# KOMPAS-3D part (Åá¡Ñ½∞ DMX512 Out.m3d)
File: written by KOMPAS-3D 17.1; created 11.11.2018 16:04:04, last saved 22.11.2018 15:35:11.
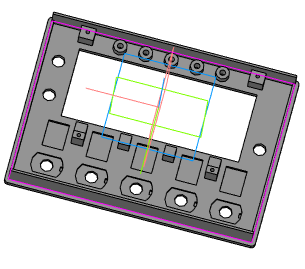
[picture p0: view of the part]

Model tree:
1. Эскиз:1
2. Элемент выдавливания:1
     Расстояние 1 = 2.4
3. Эскиз:2
4. Элемент выдавливания:2
     Расстояние 2 = 0.8
5. Эскиз:3
6. Элемент выдавливания:4
     Расстояние 2 = 2.2
7. Эскиз:4
8. Элемент выдавливания:5
     Расстояние 2 = 1
9. Эскиз:5
10. Элемент выдавливания:6
     Расстояние 1 = 3.9
11. Эскиз:6
12. Элемент выдавливания:7
     Расстояние 2 = 5.5
13. Эскиз:7
14. Элемент выдавливания:8
     Расстояние 2 = 5.5
15. Эскиз:8
16. Элемент выдавливания:9
     Расстояние 1 = 7.1
17. Эскиз:9
18. Элемент выдавливания:10
     Расстояние 2 = 7
19. Эскиз:10
20. Элемент выдавливания:11
     Расстояние 1 = 1.65
21. Эскиз:11
22. Элемент выдавливания:12
     Расстояние 2 = 7
23. Эскиз:12
24. Элемент выдавливания:13
     Расстояние 2 = 0.4
25. Эскиз:13
26. Элемент выдавливания:14
     Толщина стенки 1 = 1.2; Расстояние 1 = 12
27. Эскиз:15
28. Элемент выдавливания:15
     Расстояние 2 = 2.4
29. Эскиз:16
30. Элемент выдавливания:16
     Толщина стенки 2 = 1.2; Расстояние 1 = 4
31. Эскиз:17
